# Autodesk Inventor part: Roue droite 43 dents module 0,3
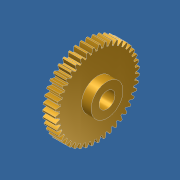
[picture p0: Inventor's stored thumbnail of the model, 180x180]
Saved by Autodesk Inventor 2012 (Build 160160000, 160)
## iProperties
Created: 2011-10
Part Number: Roue droite 43 dents module 0,3
Document SubType Name: Modeling
Designer: Laur
Density: 1 g/cm^3
Material: Par défaut
Author: Laur
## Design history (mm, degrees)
derived "roue droite de vis arbrée.iam"
node "Solide1"
node "Corps solides"
node "Corps surfaciques"
node "roue droite sur vis arbrée.ipt:1"
sketch "Engrenages cylindriques:1::Engrenage cylindrique2:1"
